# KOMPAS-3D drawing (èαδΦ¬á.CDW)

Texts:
  Крышка        выходного вала
  Noncommercial version
  Normal
  Symbol type B
  1. Неуказанные литейные радиусы 3 мм
  2. Формовочные уклоны 5
  Коснуться резцом дополучения
  опорной поверхности
  Ra3.2
  Ra12.5
  Крышка
  выходного вала
  СЧ15 ГОСТ 1412-79
Dimensions and other numbers on the sheet: 110; 130; 1; 0,3; 98; 78; 60; 6; 140; 6 отверстий; 0,04; 7; 4; 16; 20,6; 11,3; 117; 1:1; 0; 2; 3; 5; 8; 9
